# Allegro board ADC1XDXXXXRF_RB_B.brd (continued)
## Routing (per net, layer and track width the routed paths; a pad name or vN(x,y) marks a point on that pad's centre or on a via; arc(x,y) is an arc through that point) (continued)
FMC_DQ-5: length 142
  TOP w0.102: U5.C1 114.22,102.25 v1(113.71,102.76)
  SIG1 w0.102: v1(113.71,102.76) 114.1,103.15 114.1,103.4 102.59,114.91 66.5,114.91 66.28,115.13 66.28,115.42 66.18,115.52 65.98,115.52 65.87,115.42 65.87,115.13 65.65,114.91 65.28,114.91 65.06,115.13 65.06,115.42 64.96,115.52 64.76,115.52 64.65,115.42 64.65,115.13 64.43,114.91 64.06,114.91 63.84,115.13 63.84,115.42 63.74,115.52 63.54,115.52 63.44,115.42 63.44,115.13 63.21,114.91 62.84,114.91 62.62,115.13 62.62,115.42 62.52,115.52 62.32,115.52 62.22,115.42 62.22,115.13 62,114.91 61.62,114.91 61.4,115.13 61.4,115.42 61.3,115.52 61.1,115.52 61,115.42 61,115.13 60.78,114.91 60.4,114.91 60.18,115.13 60.18,115.42 60.08,115.52 59.88,115.52 59.78,115.42 59.78,115.13 59.56,114.91 59.19,114.91 58.96,115.13 58.96,115.42 58.86,115.52 58.66,115.52 58.56,115.42 58.56,115.13 58.34,114.91 57.97,114.91 57.75,115.13 57.75,115.42 57.64,115.52 57.44,115.52 57.34,115.42 57.34,115.13 57.12,114.91 56.75,114.91 56.53,115.13 56.53,115.42 56.42,115.52 56.22,115.52 56.12,115.42 56.12,115.13 55.9,114.91 55.53,114.91 55.31,115.13 55.31,115.42 55.21,115.52 55,115.52 54.9,115.42 54.9,115.13 54.68,114.91 54.31,114.91 54.09,115.13 54.09,115.42 53.99,115.52 53.78,115.52 53.68,115.42 53.68,115.13 53.46,114.91 53.09,114.91 52.87,115.13 52.87,115.42 52.77,115.52 52.56,115.52 52.46,115.42 52.46,115.13 52.24,114.91 51.87,114.91 51.65,115.13 51.65,115.42 51.55,115.52 51.34,115.52 51.24,115.42 51.24,115.13 51.02,114.91 50.65,114.91 50.43,115.13 50.43,115.42 50.33,115.52 50.13,115.52 50.02,115.42 50.02,115.13 49.8,114.91 49.43,114.91 49.21,115.13 49.21,115.42 49.11,115.52 48.91,115.52 48.8,115.42 48.8,115.13 48.58,114.91 48.21,114.91 47.99,115.13 47.99,115.42 47.89,115.52 47.69,115.52 47.59,115.42 47.59,115.13 47.37,114.91 46.99,114.91 46.77,115.13 46.77,115.42 46.67,115.52 46.47,115.52 46.37,115.42 46.37,115.13 46.15,114.91 11.65,114.91 11.53,114.79 11.53,106.35 11.66,106.22 19.35,106.22 19.46,106.32 19.46,106.65 19.35,106.76 v3(18.41,106.76)
  BOTTOM w0.102: FMC.K29 v3(18.41,106.76)
FMC_DQ-6: length 142
  TOP w0.102: v1(115.72,98.75) U5.F3
  SIG1 w0.102: v1(115.72,98.75) 115.86,98.75 116.12,98.49 116.12,94.56 115.9,94.35 109.45,94.35 98.84,104.95 62.94,104.95 62.83,105.05 62.83,106.15 62.61,106.38 62.24,106.38 62.02,106.15 62.02,105.05 61.92,104.95 61.72,104.95 61.61,105.05 61.61,106.15 61.39,106.38 61.02,106.38 60.8,106.15 60.8,105.05 60.7,104.95 60.5,104.95 60.4,105.05 60.4,106.1 60.17,106.32 59.8,106.32 59.58,106.1 59.58,105.05 59.48,104.95 59.28,104.95 59.18,105.05 59.18,106.1 58.96,106.32 58.58,106.32 58.36,106.1 58.36,105.05 58.26,104.95 58.06,104.95 57.96,105.05 57.96,106.1 57.74,106.32 57.36,106.32 57.14,106.1 57.14,105.05 57.04,104.95 56.84,104.95 56.74,105.05 56.74,106.1 56.52,106.32 56.15,106.32 55.92,106.1 55.92,105.05 55.82,104.95 55.62,104.95 55.52,105.05 55.52,106.1 55.3,106.32 54.93,106.32 54.71,106.1 54.71,105.05 54.6,104.95 54.4,104.95 54.3,105.05 54.3,106.1 54.08,106.32 53.71,106.32 53.49,106.1 53.49,105.05 53.38,104.95 53.18,104.95 53.08,105.05 53.08,106.1 52.86,106.32 52.49,106.32 52.27,106.1 52.27,105.05 52.17,104.95 51.96,104.95 51.86,105.05 51.86,106.1 51.64,106.32 51.27,106.32 51.05,106.1 51.05,105.05 50.95,104.95 50.74,104.95 50.64,105.05 50.64,106.1 50.42,106.32 50.05,106.32 49.83,106.1 49.83,105.05 49.73,104.95 49.52,104.95 49.42,105.05 49.42,106.1 49.2,106.32 48.83,106.32 48.61,106.1 48.61,105.05 48.51,104.95 48.3,104.95 48.2,105.05 48.2,106.1 47.98,106.32 47.61,106.32 47.39,106.1 47.39,105.05 47.29,104.95 47.09,104.95 46.98,105.05 46.98,106.1 46.76,106.32 46.39,106.32 46.17,106.1 46.17,105.05 46.07,104.95 18.52,104.95 18.41,105.05 v3(18.41,105.49)
  BOTTOM w0.102: FMC.J28 v3(18.41,105.49)
FMC_DQ-7: length 142.1
  TOP w0.102: v1(115.72,97.74) U5.G3
  SIG2 w0.102: v1(115.72,97.74) 115.72,97.48 115.59,97.35 104.59,97.35 96.99,104.95 90.98,104.95 90.88,105.05 90.88,105.37 90.66,105.59 90.29,105.59 90.07,105.37 90.07,105.05 89.97,104.95 89.76,104.95 89.66,105.05 89.66,105.37 89.44,105.59 89.07,105.59 88.85,105.37 88.85,105.05 88.75,104.95 88.54,104.95 88.44,105.05 88.44,105.37 88.22,105.59 87.85,105.59 87.63,105.37 87.63,105.05 87.53,104.95 87.33,104.95 87.22,105.05 87.22,105.39 87,105.61 86.63,105.61 86.41,105.39 86.41,105.05 86.31,104.95 86.11,104.95 86,105.05 86,105.39 85.78,105.61 85.41,105.61 85.19,105.39 85.19,105.05 85.09,104.95 84.89,104.95 84.79,105.05 84.79,105.39 84.56,105.61 84.19,105.61 83.97,105.39 83.97,105.05 83.87,104.95 83.67,104.95 83.57,105.05 83.57,105.39 83.35,105.61 82.97,105.61 82.75,105.39 82.75,105.05 82.65,104.95 82.45,104.95 82.35,105.05 82.35,105.39 82.13,105.61 81.75,105.61 81.53,105.39 81.53,105.05 81.43,104.95 81.23,104.95 81.13,105.05 81.13,105.39 80.91,105.61 80.54,105.61 80.31,105.39 80.31,105.05 80.21,104.95 80.01,104.95 79.91,105.05 79.91,105.39 79.69,105.61 79.32,105.61 79.1,105.39 79.1,105.05 78.99,104.95 78.79,104.95 78.69,105.05 78.69,105.39 78.47,105.61 78.1,105.61 77.88,105.39 77.88,105.05 77.77,104.95 77.57,104.95 77.47,105.05 77.47,105.39 77.25,105.61 76.88,105.61 76.66,105.39 76.66,105.05 76.56,104.95 76.35,104.95 76.25,105.05 76.25,105.39 76.03,105.61 75.66,105.61 75.44,105.39 75.44,105.05 75.34,104.95 75.13,104.95 75.03,105.05 75.03,105.39 74.81,105.61 74.44,105.61 74.22,105.39 74.22,105.05 74.12,104.95 73.91,104.95 73.81,105.05 73.81,105.39 73.59,105.61 73.22,105.61 73,105.39 73,105.05 72.9,104.95 72.69,104.95 72.59,105.05 72.59,105.39 72.37,105.61 72,105.61 71.78,105.39 71.78,105.05 71.68,104.95 71.48,104.95 71.37,105.05 71.37,105.39 71.15,105.61 70.78,105.61 70.56,105.39 70.56,105.05 70.46,104.95 70.26,104.95 70.15,105.05 70.15,105.39 69.93,105.61 69.56,105.61 69.34,105.39 69.34,105.05 69.24,104.95 69.04,104.95 68.94,105.05 68.94,105.39 68.72,105.61 68.34,105.61 68.12,105.39 68.12,105.05 68.02,104.95 67.82,104.95 67.72,105.05 67.72,105.39 67.5,105.61 67.12,105.61 66.9,105.39 66.9,105.05 66.8,104.95 66.6,104.95 66.5,105.05 66.5,105.39 66.28,105.61 65.9,105.61 65.68,105.39 65.68,105.05 65.58,104.95 65.38,104.95 65.28,105.05 65.28,105.39 65.06,105.61 64.69,105.61 64.47,105.39 64.47,105.05 64.36,104.95 64.16,104.95 64.06,105.05 64.06,105.39 63.84,105.61 63.47,105.61 63.25,105.39 63.25,105.05 63.14,104.95 62.94,104.95 62.84,105.05 62.84,105.39 62.62,105.61 62.25,105.61 62.03,105.39 62.03,105.05 61.93,104.95 61.72,104.95 61.62,105.05 61.62,105.39 61.4,105.61 61.03,105.61 60.81,105.39 60.81,105.05 60.71,104.95 60.5,104.95 60.4,105.05 60.4,105.39 60.18,105.61 59.81,105.61 59.59,105.39 59.59,105.05 59.49,104.95 59.28,104.95 59.18,105.05 59.18,105.39 58.96,105.61 58.59,105.61 58.37,105.39 58.37,105.05 58.27,104.95 58.06,104.95 57.96,105.05 57.96,105.39 57.74,105.61 57.37,105.61 57.15,105.39 57.15,105.05 57.05,104.95 56.85,104.95 56.74,105.05 56.74,105.39 56.52,105.61 56.15,105.61 55.93,105.39 55.93,105.05 55.83,104.95 55.63,104.95 55.52,105.05 55.52,105.39 55.3,105.61 54.93,105.61 54.71,105.39 54.71,105.05 54.61,104.95 54.41,104.95 54.31,105.05 54.31,105.39 54.08,105.61 53.71,105.61 53.49,105.39 53.49,105.05 53.39,104.95 53.19,104.95 53.09,105.05 53.09,105.39 52.87,105.61 52.49,105.61 52.27,105.39 52.27,105.05 52.17,104.95 51.97,104.95 51.87,105.05 51.87,105.39 51.65,105.61 51.27,105.61 51.05,105.39 51.05,105.05 50.95,104.95 50.75,104.95 50.65,105.05 50.65,105.39 50.43,105.61 50.06,105.61 49.83,105.39 49.83,105.05 49.73,104.95 49.53,104.95 49.43,105.05 49.43,105.39 49.21,105.61 48.84,105.61 48.62,105.39 48.62,105.05 48.51,104.95 48.31,104.95 48.21,105.05 48.21,105.39 47.99,105.61 47.62,105.61 47.4,105.39 47.4,105.05 47.29,104.95 47.09,104.95 46.99,105.05 46.99,105.39 46.77,105.61 46.4,105.61 46.18,105.39 46.18,105.05 46.08,104.95 14.35,104.95 14.2,105.11 14.2,105.31 14.38,105.49 v3(14.61,105.49)
  BOTTOM w0.102: FMC.F29 v3(14.61,105.49)
FMC_DQ-8: length 142.1
  TOP w0.102: v1(113.72,99.75) U5.F1
  SIG2 w0.102: v3(12.06,105.49) 12.19,105.49 12.29,105.38 12.29,105.05 12.19,104.95 10.41,104.95 10.26,105.11 10.26,109.69 10.4,109.83 14.05,109.83 15.32,108.56 46.16,108.56 46.38,108.78 46.38,109.02 46.48,109.12 46.69,109.12 46.79,109.02 46.79,108.78 47.01,108.56 47.38,108.56 47.6,108.78 47.6,109.02 47.7,109.12 47.9,109.12 48.01,109.02 48.01,108.78 48.23,108.56 48.6,108.56 48.82,108.78 48.82,109.02 48.92,109.12 49.12,109.12 49.23,109.02 49.23,108.78 49.45,108.56 49.82,108.56 50.04,108.78 50.04,109.02 50.14,109.12 50.34,109.12 50.44,109.02 50.44,108.78 50.66,108.56 51.04,108.56 51.26,108.78 51.26,109.02 51.36,109.12 51.56,109.12 51.66,109.02 51.66,108.78 51.88,108.56 52.26,108.56 52.48,108.78 52.48,109.02 52.58,109.12 52.78,109.12 52.88,109.02 52.88,108.78 53.1,108.56 53.48,108.56 53.7,108.78 53.7,109.02 53.8,109.12 54,109.12 54.1,109.02 54.1,108.78 54.32,108.56 54.69,108.56 54.91,108.78 54.91,109.02 55.02,109.12 55.22,109.12 55.32,109.02 55.32,108.78 55.54,108.56 55.91,108.56 56.13,108.78 56.13,109.02 56.24,109.12 56.44,109.12 56.54,109.02 56.54,108.78 56.76,108.56 57.13,108.56 57.35,108.78 57.35,109.02 57.45,109.12 57.66,109.12 57.76,109.02 57.76,108.78 57.98,108.56 58.35,108.56 58.57,108.78 58.57,109.02 58.67,109.12 58.88,109.12 58.98,109.02 58.98,108.78 59.2,108.56 59.57,108.56 59.79,108.78 59.79,109.02 59.89,109.12 60.1,109.12 60.2,109.02 60.2,108.78 60.42,108.56 60.79,108.56 61.01,108.78 61.01,109.02 61.11,109.12 61.32,109.12 61.42,109.02 61.42,108.78 61.64,108.56 62.01,108.56 62.23,108.78 62.23,109.02 62.33,109.12 62.53,109.12 62.64,109.02 62.64,108.78 62.86,108.56 63.23,108.56 63.45,108.78 63.45,109.02 63.55,109.12 63.75,109.12 63.86,109.02 63.86,108.78 64.08,108.56 64.45,108.56 64.67,108.78 64.67,109.02 64.77,109.12 64.97,109.12 65.07,109.02 65.07,108.78 65.3,108.56 65.67,108.56 65.89,108.78 65.89,109.02 65.99,109.12 66.19,109.12 66.29,109.02 66.29,108.78 66.51,108.56 66.89,108.56 67.11,108.78 67.11,109.02 67.21,109.12 67.41,109.12 67.51,109.02 67.51,108.78 67.73,108.56 68.11,108.56 68.33,108.78 68.33,109.02 68.43,109.12 68.63,109.12 68.73,109.02 68.73,108.78 68.95,108.56 69.32,108.56 69.55,108.78 69.55,109.02 69.65,109.12 69.85,109.12 69.95,109.02 69.95,108.78 70.17,108.56 70.54,108.56 70.76,108.78 70.76,109.02 70.87,109.12 71.07,109.12 71.17,109.02 71.17,108.78 71.39,108.56 71.76,108.56 71.98,108.78 71.98,109.02 72.09,109.12 72.29,109.12 72.39,109.02 72.39,108.78 72.61,108.56 72.98,108.56 73.2,108.78 73.2,109.02 73.3,109.12 73.51,109.12 73.61,109.02 73.61,108.78 73.83,108.56 74.2,108.56 74.42,108.78 74.42,109.02 74.52,109.12 74.73,109.12 74.83,109.02 74.83,108.78 75.05,108.56 75.42,108.56 75.64,108.78 75.64,109.02 75.74,109.12 75.95,109.12 76.05,109.02 76.05,108.78 76.27,108.56 76.64,108.56 76.86,108.78 76.86,109.02 76.96,109.12 77.17,109.12 77.27,109.02 77.27,108.78 77.49,108.56 77.86,108.56 78.08,108.78 78.08,109.02 78.18,109.12 78.38,109.12 78.49,109.02 78.49,108.78 78.71,108.56 79.08,108.56 79.3,108.78 79.3,108.99 79.4,109.09 79.6,109.09 79.71,108.99 79.71,108.78 79.93,108.56 80.3,108.56 80.52,108.78 80.52,108.99 80.62,109.09 80.82,109.09 80.92,108.99 80.92,108.78 81.14,108.56 81.52,108.56 81.74,108.78 81.74,108.99 81.84,109.09 82.04,109.09 82.14,108.99 82.14,108.78 82.36,108.56 82.74,108.56 82.96,108.78 82.96,108.99 83.06,109.09 83.26,109.09 83.36,108.99 83.36,108.78 83.58,108.56 83.96,108.56 84.18,108.78 84.18,108.99 84.28,109.09 84.48,109.09 84.58,108.99 84.58,108.78 84.8,108.56 85.17,108.56 85.39,108.78 85.39,108.99 85.5,109.09 85.7,109.09 85.8,108.99 85.8,108.78 86.02,108.56 86.39,108.56 86.61,108.78 86.61,108.99 86.72,109.09 86.92,109.09 87.02,108.99 87.02,108.78 87.24,108.56 87.61,108.56 87.83,108.78 87.83,108.99 87.93,109.09 88.14,109.09 88.24,108.99 88.24,108.78 88.46,108.56 95.22,108.56 103.62,100.15 113.31,100.15 113.71,99.75 v1(113.72,99.75)
  BOTTOM w0.102: FMC.E28 v3(12.06,105.49)
FMC_DQ-9: length 142.1
  TOP w0.102: U5.C10 v1(122.71,102.76)
  SIG2 w0.102: v1(122.71,102.76) 122.31,102.36 121.46,102.36 121.1,102 121.1,100.47 120.99,100.35 116.54,100.35 115.54,101.35 103.71,101.35 95.03,110.03 89.76,110.03 89.66,110.13 89.66,110.4 89.44,110.62 89.07,110.62 88.85,110.4 88.85,110.13 88.75,110.03 88.54,110.03 88.44,110.13 88.44,110.4 88.22,110.62 87.85,110.62 87.63,110.4 87.63,110.13 87.53,110.03 87.33,110.03 87.22,110.13 87.22,110.4 87,110.62 86.63,110.62 86.41,110.4 86.41,110.13 86.31,110.03 86.11,110.03 86,110.13 86,110.4 85.78,110.62 85.41,110.62 85.19,110.4 85.19,110.13 85.09,110.03 84.89,110.03 84.79,110.13 84.79,110.4 84.56,110.62 84.19,110.62 83.97,110.4 83.97,110.13 83.87,110.03 83.67,110.03 83.57,110.13 83.57,110.42 83.35,110.64 82.97,110.64 82.75,110.42 82.75,110.13 82.65,110.03 82.45,110.03 82.35,110.13 82.35,110.42 82.13,110.64 81.75,110.64 81.53,110.42 81.53,110.13 81.43,110.03 81.23,110.03 81.13,110.13 81.13,110.42 80.91,110.64 80.54,110.64 80.31,110.42 80.31,110.13 80.21,110.03 80.01,110.03 79.91,110.13 79.91,110.42 79.69,110.64 79.32,110.64 79.1,110.42 79.1,110.13 78.99,110.03 78.79,110.03 78.69,110.13 78.69,110.42 78.47,110.64 78.1,110.64 77.88,110.42 77.88,110.13 77.77,110.03 77.57,110.03 77.47,110.13 77.47,110.42 77.25,110.64 76.88,110.64 76.66,110.42 76.66,110.13 76.56,110.03 76.35,110.03 76.25,110.13 76.25,110.42 76.03,110.64 75.66,110.64 75.44,110.42 75.44,110.13 75.34,110.03 75.13,110.03 75.03,110.13 75.03,110.42 74.81,110.64 74.44,110.64 74.22,110.42 74.22,110.13 74.12,110.03 73.91,110.03 73.81,110.13 73.81,110.42 73.59,110.64 73.22,110.64 73,110.42 73,110.13 72.9,110.03 72.69,110.03 72.59,110.13 72.59,110.42 72.37,110.64 72,110.64 71.78,110.42 71.78,110.13 71.68,110.03 71.48,110.03 71.37,110.13 71.37,110.42 71.15,110.64 70.78,110.64 70.56,110.42 70.56,110.13 70.46,110.03 70.26,110.03 70.15,110.13 70.15,110.42 69.93,110.64 69.56,110.64 69.34,110.42 69.34,110.13 69.24,110.03 69.04,110.03 68.94,110.13 68.94,110.42 68.72,110.64 68.34,110.64 68.12,110.42 68.12,110.13 68.02,110.03 67.82,110.03 67.72,110.13 67.72,110.42 67.5,110.64 67.12,110.64 66.9,110.42 66.9,110.13 66.8,110.03 66.6,110.03 66.5,110.13 66.5,110.42 66.28,110.64 65.9,110.64 65.68,110.42 65.68,110.13 65.58,110.03 65.38,110.03 65.28,110.13 65.28,110.42 65.06,110.64 64.69,110.64 64.47,110.42 64.47,110.13 64.36,110.03 64.16,110.03 64.06,110.13 64.06,110.42 63.84,110.64 63.47,110.64 63.25,110.42 63.25,110.13 63.14,110.03 62.94,110.03 62.84,110.13 62.84,110.42 62.62,110.64 62.25,110.64 62.03,110.42 62.03,110.13 61.93,110.03 61.72,110.03 61.62,110.13 61.62,110.42 61.4,110.64 61.03,110.64 60.81,110.42 60.81,110.13 60.71,110.03 60.5,110.03 60.4,110.13 60.4,110.42 60.18,110.64 59.81,110.64 59.59,110.42 59.59,110.13 59.49,110.03 59.28,110.03 59.18,110.13 59.18,110.42 58.96,110.64 58.59,110.64 58.37,110.42 58.37,110.13 58.27,110.03 58.06,110.03 57.96,110.13 57.96,110.42 57.74,110.64 57.37,110.64 57.15,110.42 57.15,110.13 57.05,110.03 56.85,110.03 56.74,110.13 56.74,110.42 56.52,110.64 56.15,110.64 55.93,110.42 55.93,110.13 55.83,110.03 55.63,110.03 55.52,110.13 55.52,110.42 55.3,110.64 54.93,110.64 54.71,110.42 54.71,110.13 54.61,110.03 54.41,110.03 54.31,110.13 54.31,110.42 54.08,110.64 53.71,110.64 53.49,110.42 53.49,110.13 53.39,110.03 53.19,110.03 53.09,110.13 53.09,110.42 52.87,110.64 52.49,110.64 52.27,110.42 52.27,110.13 52.17,110.03 51.97,110.03 51.87,110.13 51.87,110.42 51.65,110.64 51.27,110.64 51.05,110.42 51.05,110.13 50.95,110.03 50.75,110.03 50.65,110.13 50.65,110.42 50.43,110.64 50.06,110.64 49.83,110.42 49.83,110.13 49.73,110.03 49.53,110.03 49.43,110.13 49.43,110.42 49.21,110.64 48.84,110.64 48.62,110.42 48.62,110.13 48.51,110.03 48.31,110.03 48.21,110.13 48.21,110.42 47.99,110.64 47.62,110.64 47.4,110.42 47.4,110.13 47.29,110.03 47.09,110.03 46.99,110.13 46.99,110.42 46.77,110.64 46.4,110.64 46.18,110.42 46.18,110.13 46.08,110.03 18.95,110.03 v3(18.41,110.57)
  BOTTOM w0.102: FMC.K32 v3(18.41,110.57)
FMC_DQ-10: length 142
  TOP w0.102: v1(113.72,97.74) U5.G1
  SIG1 w0.102: v3(17.14,109.3) 17.68,108.76 19.19,108.76 20.46,110.03 47.26,110.03 47.37,110.13 47.37,110.47 47.59,110.69 47.96,110.69 48.18,110.47 48.18,110.13 48.28,110.03 48.48,110.03 48.58,110.13 48.58,110.47 48.8,110.69 49.18,110.69 49.4,110.47 49.4,110.13 49.5,110.03 49.7,110.03 49.8,110.13 49.8,110.47 50.02,110.69 50.4,110.69 50.62,110.47 50.62,110.13 50.72,110.03 50.92,110.03 51.02,110.13 51.02,110.47 51.24,110.69 51.62,110.69 51.84,110.47 51.84,110.13 51.94,110.03 52.14,110.03 52.24,110.13 52.24,110.47 52.46,110.69 52.83,110.69 53.05,110.47 53.05,110.13 53.16,110.03 53.36,110.03 53.46,110.13 53.46,110.47 53.68,110.69 54.05,110.69 54.27,110.47 54.27,110.13 54.38,110.03 54.58,110.03 54.68,110.13 54.68,110.47 54.9,110.69 55.27,110.69 55.49,110.47 55.49,110.13 55.59,110.03 55.8,110.03 55.9,110.13 55.9,110.47 56.12,110.69 56.49,110.69 56.71,110.47 56.71,110.13 56.81,110.03 57.02,110.03 57.12,110.13 57.12,110.47 57.34,110.69 57.71,110.69 57.93,110.47 57.93,110.13 58.03,110.03 58.24,110.03 58.34,110.13 58.34,110.47 58.56,110.69 58.93,110.69 59.15,110.47 59.15,110.13 59.25,110.03 59.46,110.03 59.56,110.13 59.56,110.45 59.78,110.67 60.15,110.67 60.37,110.45 60.37,110.13 60.47,110.03 60.67,110.03 60.78,110.13 60.78,110.45 61,110.67 61.37,110.67 61.59,110.45 61.59,110.13 61.69,110.03 61.89,110.03 62,110.13 62,110.45 62.22,110.67 62.59,110.67 62.81,110.45 62.81,110.13 62.91,110.03 63.11,110.03 63.21,110.13 63.21,110.45 63.44,110.67 63.81,110.67 64.03,110.45 64.03,110.13 64.13,110.03 64.33,110.03 64.43,110.13 64.43,110.45 64.65,110.67 65.03,110.67 65.25,110.45 65.25,110.13 65.35,110.03 65.55,110.03 65.65,110.13 65.65,110.45 65.87,110.67 66.25,110.67 66.47,110.45 66.47,110.13 66.57,110.03 66.77,110.03 66.87,110.13 66.87,110.45 67.09,110.67 67.46,110.67 67.69,110.45 67.69,110.13 67.79,110.03 67.99,110.03 68.09,110.13 68.09,110.45 68.31,110.67 68.68,110.67 68.9,110.45 68.9,110.13 69.01,110.03 69.21,110.03 69.31,110.13 69.31,110.45 69.53,110.67 69.9,110.67 70.12,110.45 70.12,110.13 70.23,110.03 70.43,110.03 70.53,110.13 70.53,110.45 70.75,110.67 71.12,110.67 71.34,110.45 71.34,110.13 71.44,110.03 71.65,110.03 71.75,110.13 71.75,110.45 71.97,110.67 72.34,110.67 72.56,110.45 72.56,110.13 72.66,110.03 72.87,110.03 72.97,110.13 72.97,110.45 73.19,110.67 73.56,110.67 73.78,110.45 73.78,110.13 73.88,110.03 74.09,110.03 74.19,110.13 74.19,110.45 74.41,110.67 74.78,110.67 75,110.45 75,110.13 75.1,110.03 75.31,110.03 75.41,110.13 75.41,110.45 75.63,110.67 76,110.67 76.22,110.45 76.22,110.13 76.32,110.03 76.52,110.03 76.63,110.13 76.63,110.45 76.85,110.67 77.22,110.67 77.44,110.45 77.44,110.13 77.54,110.03 77.74,110.03 77.85,110.13 77.85,110.45 78.07,110.67 78.44,110.67 78.66,110.45 78.66,110.13 78.76,110.03 78.96,110.03 79.06,110.13 79.06,110.45 79.28,110.67 79.66,110.67 79.88,110.45 79.88,110.13 79.98,110.03 80.18,110.03 80.28,110.13 80.28,110.45 80.5,110.67 80.88,110.67 81.1,110.45 81.1,110.13 81.2,110.03 81.4,110.03 81.5,110.13 81.5,110.45 81.72,110.67 82.1,110.67 82.32,110.45 82.32,110.13 82.42,110.03 82.62,110.03 82.72,110.13 82.72,110.45 82.94,110.67 83.31,110.67 83.53,110.45 83.53,110.13 83.64,110.03 83.84,110.03 83.94,110.13 83.94,110.45 84.16,110.67 84.53,110.67 84.75,110.45 84.75,110.13 84.86,110.03 85.06,110.03 85.16,110.13 85.16,110.45 85.38,110.67 85.75,110.67 85.97,110.45 85.97,110.13 86.07,110.03 86.28,110.03 86.38,110.13 86.38,110.45 86.6,110.67 86.97,110.67 87.19,110.45 87.19,110.13 87.29,110.03 87.5,110.03 87.6,110.13 87.6,110.45 87.82,110.67 88.19,110.67 88.41,110.45 88.41,110.13 88.51,110.03 88.72,110.03 88.82,110.13 88.82,110.45 89.04,110.67 89.41,110.67 89.63,110.45 89.63,110.13 89.73,110.03 89.94,110.03 90.04,110.13 90.04,110.45 90.26,110.67 90.63,110.67 90.85,110.45 90.85,110.13 90.95,110.03 91.15,110.03 91.26,110.13 91.26,110.45 91.48,110.67 91.85,110.67 92.07,110.45 92.07,110.13 92.17,110.03 92.37,110.03 92.48,110.13 92.48,110.45 92.7,110.67 93.07,110.67 93.29,110.45 93.29,110.13 93.39,110.03 93.59,110.03 93.69,110.13 93.69,110.45 93.92,110.67 94.29,110.67 94.51,110.45 94.51,110.13 94.61,110.03 94.81,110.03 94.91,110.13 94.91,110.45 95.13,110.67 95.51,110.67 95.73,110.45 95.73,110.13 95.83,110.03 96.03,110.03 96.13,110.13 96.13,110.45 96.35,110.67 96.73,110.67 96.95,110.45 96.95,110.13 97.05,110.03 97.25,110.03 97.35,110.13 97.35,110.45 97.57,110.67 97.94,110.67 98.17,110.45 98.17,110.13 98.27,110.03 99.86,110.03 111.83,98.06 113.4,98.06 v1(113.72,97.74)
  BOTTOM w0.102: FMC.J31 v3(17.14,109.3)
FMC_DQ-11: length 142.1
  TOP w0.102: v1(115.72,96.74) U5.H3
  SIG2 w0.102: v1(115.72,96.74) 116.15,96.74 116.56,97.16 116.81,97.16 117.12,97.46 117.12,98.02 116.99,98.15 104.55,98.15 96.67,106.02 56.76,106.02 56.54,106.24 56.54,107.62 56.44,107.72 56.24,107.72 56.13,107.62 56.13,106.24 55.91,106.02 55.54,106.02 55.32,106.24 55.32,107.62 55.22,107.72 55.02,107.72 54.91,107.62 54.91,106.24 54.69,106.02 54.32,106.02 54.1,106.24 54.1,107.62 54,107.72 53.8,107.72 53.7,107.62 53.7,106.24 53.48,106.02 53.1,106.02 52.88,106.24 52.88,107.59 52.78,107.7 52.58,107.7 52.48,107.59 52.48,106.24 52.26,106.02 51.88,106.02 51.66,106.24 51.66,107.59 51.56,107.7 51.36,107.7 51.26,107.59 51.26,106.24 51.04,106.02 50.66,106.02 50.44,106.24 50.44,107.59 50.34,107.7 50.14,107.7 50.04,107.59 50.04,106.24 49.82,106.02 49.45,106.02 49.23,106.24 49.23,107.59 49.12,107.7 48.92,107.7 48.82,107.59 48.82,106.24 48.6,106.02 48.23,106.02 48.01,106.24 48.01,107.59 47.9,107.7 47.7,107.7 47.6,107.59 47.6,106.24 47.38,106.02 47.01,106.02 46.79,106.24 46.79,107.59 46.69,107.7 46.48,107.7 46.38,107.59 46.38,106.24 46.16,106.02 12.83,106.02 12.57,106.27 12.57,108.53 v3(13.34,109.3)
  BOTTOM w0.102: FMC.F32 v3(13.34,109.3)
FMC_DQD+0: length 142
  TOP w0.102: v1(122.72,99.75) U5.F10
  SIG3 w0.102: v1(122.72,99.75) 122.73,99.77 122.73,100.05 122.66,100.13 122.52,100.13 122.31,99.92 122.31,92.48 121.98,92.15 119.54,92.15 119.31,91.91 119.31,91.48 118.97,91.14 76.18,91.14 61.21,76.17 55.82,76.17 55.72,76.07 55.72,75.25 55.5,75.03 55.13,75.03 54.91,75.25 54.91,76.07 54.81,76.17 54.6,76.17 54.5,76.07 54.5,75.25 54.28,75.03 53.91,75.03 53.69,75.25 53.69,76.07 53.59,76.17 53.39,76.17 53.28,76.07 53.28,75.25 53.06,75.03 52.69,75.03 52.47,75.25 52.47,76.07 52.37,76.17 52.17,76.17 52.06,76.07 52.06,75.25 51.84,75.03 51.47,75.03 51.25,75.25 51.25,76.07 51.15,76.17 50.95,76.17 50.85,76.07 50.85,75.25 50.62,75.03 50.25,75.03 50.03,75.25 50.03,76.07 49.93,76.17 49.73,76.17 49.63,76.07 49.63,75.25 49.41,75.03 49.03,75.03 48.81,75.25 48.81,76.07 48.71,76.17 48.51,76.17 48.41,76.07 48.41,75.25 48.19,75.03 47.81,75.03 47.59,75.25 47.59,76.07 47.49,76.17 46.44,76.17 43.26,73 12.6,73 v3(12.06,72.47)
  BOTTOM w0.102: FMC.E2 v3(12.06,72.47)
FMC_DQD+1: length 142.1
  TOP w0.102: U5.E9 122.18,100.24 v1(121.7,99.76)
  SIG3 w0.102: v1(121.7,99.76) 121.28,99.34 72.56,99.34 72.14,98.92 72.14,97.63 72.03,97.53 71.7,97.53 71.48,97.31 71.48,96.94 71.7,96.71 72.03,96.71 72.14,96.61 72.14,96.41 72.03,96.31 71.7,96.31 71.48,96.09 71.48,95.72 71.7,95.5 72.03,95.5 72.14,95.39 72.14,95.19 72.03,95.09 71.7,95.09 71.48,94.87 71.48,94.5 71.7,94.28 72.03,94.28 72.14,94.17 72.14,93.97 72.03,93.87 71.7,93.87 71.48,93.65 71.48,93.28 71.7,93.06 72.03,93.06 72.14,92.96 72.14,92.75 72.03,92.65 71.7,92.65 71.48,92.43 71.48,92.06 71.7,91.84 72.03,91.84 72.14,91.74 72.14,91.53 72.03,91.43 71.7,91.43 71.48,91.21 71.48,90.84 71.7,90.62 72.03,90.62 72.14,90.52 72.14,90.23 61.46,79.55 60.7,79.55 60.6,79.65 60.6,79.99 60.38,80.21 60.01,80.21 59.79,79.99 59.79,79.35 59.68,79.25 59.48,79.25 59.38,79.35 59.38,79.99 59.16,80.21 58.79,80.21 58.57,79.99 58.57,79.35 58.47,79.25 58.26,79.25 58.16,79.35 58.16,79.99 57.94,80.21 57.57,80.21 57.35,79.99 57.35,79.35 57.25,79.25 57.04,79.25 56.94,79.35 56.94,79.99 56.72,80.21 56.35,80.21 56.13,79.99 56.13,79.35 56.03,79.25 55.82,79.25 55.72,79.35 55.72,79.99 55.5,80.21 55.13,80.21 54.91,79.99 54.91,79.35 54.81,79.25 54.6,79.25 54.5,79.35 54.5,79.99 54.28,80.21 53.91,80.21 53.69,79.99 53.69,79.38 53.59,79.27 53.39,79.27 53.28,79.38 53.28,79.99 53.06,80.21 52.69,80.21 52.47,79.99 52.47,79.38 52.37,79.27 52.17,79.27 52.06,79.38 52.06,79.99 51.84,80.21 51.47,80.21 51.25,79.99 51.25,79.38 51.15,79.27 50.95,79.27 50.85,79.38 50.85,79.99 50.62,80.21 50.25,80.21 50.03,79.99 50.03,79.38 49.93,79.27 49.73,79.27 49.63,79.38 49.63,79.99 49.41,80.21 49.03,80.21 48.81,79.99 48.81,79.38 48.71,79.27 48.51,79.27 48.41,79.38 48.41,79.99 48.19,80.21 47.81,80.21 47.59,79.99 47.59,79.65 47.49,79.55 46.54,79.55 45.37,80.72 19.34,80.72 19.02,80.4 19.02,79.47 19.68,78.82 v3(19.68,78.82)
  BOTTOM w0.102: FMC.K7 v3(19.68,78.82)
FMC_DQD+2: length 142.1
  TOP w0.102: v1(120.72,98.75) U5.F8
  SIG3 w0.102: v1(120.72,98.75) 121.31,98.15 121.31,94.3 120.15,93.14 118.5,93.14 118.31,92.95 118.31,92.39 118.06,92.14 75.76,92.14 62.08,78.46 60.09,78.46 59.99,78.36 59.99,77.33 59.77,77.11 59.4,77.11 59.18,77.33 59.18,78.36 59.08,78.46 58.87,78.46 58.77,78.36 58.77,77.33 58.55,77.11 58.18,77.11 57.96,77.33 57.96,78.36 57.86,78.46 57.65,78.46 57.55,78.36 57.55,77.33 57.33,77.11 56.96,77.11 56.74,77.33 56.74,78.36 56.64,78.46 56.43,78.46 56.33,78.36 56.33,77.33 56.11,77.11 55.74,77.11 55.52,77.33 55.52,78.36 55.42,78.46 55.21,78.46 55.11,78.36 55.11,77.33 54.89,77.11 54.52,77.11 54.3,77.33 54.3,78.36 54.2,78.46 54,78.46 53.89,78.36 53.89,77.33 53.67,77.11 53.3,77.11 53.08,77.33 53.08,78.36 52.98,78.46 52.78,78.46 52.67,78.36 52.67,77.33 52.45,77.11 52.08,77.11 51.86,77.33 51.86,78.36 51.76,78.46 51.56,78.46 51.46,78.36 51.46,77.31 51.23,77.09 50.86,77.09 50.64,77.31 50.64,78.36 50.54,78.46 50.34,78.46 50.24,78.36 50.24,77.31 50.02,77.09 49.64,77.09 49.42,77.31 49.42,78.36 49.32,78.46 49.12,78.46 49.02,78.36 49.02,77.31 48.8,77.09 48.42,77.09 48.2,77.31 48.2,78.36 48.1,78.46 47.9,78.46 47.8,78.36 47.8,77.31 47.58,77.09 47.21,77.09 46.98,77.31 46.98,78.36 46.88,78.46 45.91,78.46 45.52,78.08 18.95,78.08 v3(18.41,77.55)
  BOTTOM w0.102: FMC.J6 v3(18.41,77.55)
FMC_DQD+3: length 142.1
  TOP w0.102: U5.D9 v1(121.71,101.75)
  SIG3 w0.102: v3(14.61,77.55) 15.14,78.08 16.31,78.08 16.61,78.38 16.61,79.2 16.76,79.35 17.58,79.35 17.88,79.65 17.88,80.26 18.82,81.2 46.13,81.2 46.71,80.62 47.58,80.62 47.8,80.84 47.8,81.18 47.9,81.28 48.1,81.28 48.2,81.18 48.2,80.84 48.42,80.62 48.8,80.62 49.02,80.84 49.02,81.18 49.12,81.28 49.32,81.28 49.42,81.18 49.42,80.84 49.64,80.62 50.02,80.62 50.24,80.84 50.24,81.18 50.34,81.28 50.54,81.28 50.64,81.18 50.64,80.84 50.86,80.62 51.23,80.62 51.46,80.84 51.46,81.18 51.56,81.28 51.76,81.28 51.86,81.18 51.86,80.84 52.08,80.62 52.45,80.62 52.67,80.84 52.67,81.18 52.78,81.28 52.98,81.28 53.08,81.18 53.08,80.84 53.3,80.62 53.67,80.62 53.89,80.84 53.89,81.18 54,81.28 54.2,81.28 54.3,81.18 54.3,80.84 54.52,80.62 54.89,80.62 55.11,80.84 55.11,81.18 55.21,81.28 55.42,81.28 55.52,81.18 55.52,80.84 55.74,80.62 56.11,80.62 56.33,80.84 56.33,81.18 56.43,81.28 56.64,81.28 56.74,81.18 56.74,80.84 56.96,80.62 57.33,80.62 57.55,80.84 57.55,81.15 57.65,81.25 57.86,81.25 57.96,81.15 57.96,80.84 58.18,80.62 58.55,80.62 58.77,80.84 58.77,81.15 58.87,81.25 59.08,81.25 59.18,81.15 59.18,80.84 59.4,80.62 59.77,80.62 59.99,80.84 59.99,81.15 60.09,81.25 60.29,81.25 60.4,81.15 60.4,80.84 60.62,80.62 61.39,80.62 71.07,90.3 71.07,91.82 70.85,92.04 70.54,92.04 70.43,92.14 70.43,92.35 70.54,92.45 70.85,92.45 71.07,92.67 71.07,93.04 70.85,93.26 70.54,93.26 70.43,93.36 70.43,93.56 70.54,93.67 70.85,93.67 71.07,93.89 71.07,94.26 70.85,94.48 70.54,94.48 70.43,94.58 70.43,94.78 70.54,94.89 70.85,94.89 71.07,95.11 71.07,95.48 70.85,95.7 70.54,95.7 70.43,95.8 70.43,96 70.54,96.1 70.85,96.1 71.07,96.33 71.07,96.7 70.85,96.92 70.54,96.92 70.43,97.02 70.43,97.22 70.54,97.32 70.85,97.32 71.07,97.54 71.07,97.92 70.85,98.14 70.54,98.14 70.43,98.24 70.43,98.44 70.54,98.54 70.85,98.54 71.07,98.76 71.07,99.85 71.37,100.15 119.97,100.15 120.3,100.48 120.3,100.91 120.54,101.15 120.97,101.15 121.31,101.49 121.31,101.93 121.41,102.03 121.62,102.03 121.71,101.94 v1(121.71,101.75)
  BOTTOM w0.102: FMC.F7 v3(14.61,77.55)
FMC_DQD+4: length 142.1
  TOP w0.102: U5.D8 121.22,101.24 v1(120.71,101.75)
  SIG3 w0.102: v1(120.71,101.75) 120.27,101.75 119.67,102.36 107.77,102.36 107.31,102.82 68.8,102.82 68.33,102.34 68.33,101.29 68.22,101.18 67.89,101.18 67.67,100.96 67.67,100.59 67.89,100.37 68.22,100.37 68.33,100.27 68.33,100.07 68.22,99.97 67.89,99.97 67.67,99.75 67.67,99.37 67.89,99.15 68.22,99.15 68.33,99.05 68.33,98.85 68.22,98.75 67.91,98.75 67.69,98.53 67.69,98.15 67.91,97.93 68.22,97.93 68.33,97.83 68.33,97.63 68.22,97.53 67.91,97.53 67.69,97.31 67.69,96.94 67.91,96.71 68.22,96.71 68.33,96.61 68.33,96.41 68.22,96.31 67.91,96.31 67.69,96.09 67.69,95.72 67.91,95.5 68.22,95.5 68.33,95.39 68.33,95.19 68.22,95.09 67.91,95.09 67.69,94.87 67.69,94.5 67.91,94.28 68.22,94.28 68.33,94.17 68.33,93.97 68.22,93.87 67.91,93.87 67.69,93.65 67.69,93.28 67.91,93.06 68.22,93.06 68.33,92.96 68.33,92.75 68.22,92.65 67.91,92.65 67.69,92.43 67.69,92.06 67.91,91.84 68.22,91.84 68.33,91.74 68.33,90.69 61.54,83.9 v3(61.49,83.9)
  BOTTOM w0.102: FMC.E6 12.19,77.42 11.2,77.42 10.92,77.14 10.92,75.34 11.13,75.13 13.13,75.13 13.46,74.8 13.46,74.19 13.77,73.89 51.92,73.89 61.49,83.46 v3(61.49,83.9)
FMC_DQD+5: length 142.1
  TOP w0.102: v1(119.71,103.76) 120.22,103.25 U5.B7
  SIG3 w0.102: v1(119.71,103.76) 119.31,103.36 114.52,103.36 113.79,104.09 74.55,104.09 74.44,104.19 74.44,104.48 74.22,104.7 73.85,104.7 73.63,104.48 73.63,104.19 73.53,104.09 73.33,104.09 73.22,104.19 73.22,104.48 73,104.7 72.63,104.7 72.41,104.48 72.41,104.19 72.31,104.09 72.11,104.09 72.01,104.19 72.01,104.5 71.79,104.72 71.41,104.72 71.19,104.5 71.19,104.19 71.09,104.09 70.89,104.09 70.79,104.19 70.79,104.5 70.57,104.72 70.19,104.72 69.97,104.5 69.97,104.19 69.87,104.09 69.67,104.09 69.57,104.19 69.57,104.5 69.35,104.72 68.97,104.72 68.75,104.5 68.75,104.19 68.65,104.09 67.51,104.09 67.06,103.64 67.06,102.51 66.95,102.4 66.62,102.4 66.4,102.18 66.4,101.81 66.62,101.59 66.95,101.59 67.06,101.49 67.06,101.29 66.95,101.18 66.62,101.18 66.4,100.96 66.4,100.59 66.62,100.37 66.95,100.37 67.06,100.27 67.06,100.07 66.95,99.97 66.62,99.97 66.4,99.75 66.4,99.37 66.62,99.15 66.95,99.15 67.06,99.05 67.06,98.85 66.95,98.75 66.62,98.75 66.4,98.53 66.4,98.15 66.62,97.93 66.95,97.93 67.06,97.83 67.06,97.63 66.95,97.53 66.62,97.53 66.4,97.31 66.4,96.94 66.62,96.71 66.95,96.71 67.06,96.61 67.06,96.41 66.95,96.31 66.62,96.31 66.4,96.09 66.4,95.72 66.62,95.5 66.95,95.5 67.06,95.39 67.06,95.19 66.95,95.09 66.62,95.09 66.4,94.87 66.4,94.5 66.62,94.28 66.95,94.28 67.06,94.17 67.06,93.97 66.95,93.87 66.62,93.87 66.4,93.65 66.4,93.28 66.62,93.06 66.95,93.06 67.06,92.96 67.06,92.75 66.95,92.65 66.62,92.65 66.4,92.43 66.4,92.06 66.62,91.84 66.95,91.84 67.06,91.74 67.06,90.84 59.58,83.36 58.26,83.36 58.16,83.46 58.16,83.8 57.94,84.02 57.57,84.02 57.35,83.8 57.35,83.46 57.25,83.36 57.04,83.36 56.94,83.46 56.94,83.8 56.72,84.02 56.35,84.02 56.13,83.8 56.13,83.46 56.03,83.36 55.82,83.36 55.72,83.46 55.72,83.8 55.5,84.02 55.13,84.02 54.91,83.8 54.91,83.46 54.81,83.36 54.6,83.36 54.5,83.46 54.5,83.8 54.28,84.02 53.91,84.02 53.69,83.8 53.69,83.46 53.59,83.36 53.39,83.36 53.28,83.46 53.28,83.8 53.06,84.02 52.69,84.02 52.47,83.8 52.47,83.46 52.37,83.36 52.17,83.36 52.06,83.46 52.06,83.8 51.84,84.02 51.47,84.02 51.25,83.8 51.25,83.46 51.15,83.36 50.95,83.36 50.85,83.46 50.85,83.8 50.62,84.02 50.25,84.02 50.03,83.8 50.03,83.46 49.93,83.36 49.73,83.36 49.63,83.46 49.63,83.8 49.41,84.02 49.03,84.02 48.81,83.8 48.81,83.46 48.71,83.36 48.51,83.36 48.41,83.46 48.41,83.8 48.19,84.02 47.81,84.02 47.59,83.8 47.59,83.46 47.49,83.36 20.83,83.36 19.86,84.33 19.51,84.33 19.25,84.07 19.25,83.06 v3(19.68,82.63)
  BOTTOM w0.102: v3(19.68,82.63) FMC.K10
FMC_DQD+6: length 142.1
  TOP w0.102: v1(120.52,107.34) 120.52,107.04 120.85,106.72 120.85,104.62 U5.A8
  SIG3 w0.102: v3(57.07,86.44) 56.95,86.56 56.95,88.47 57.83,89.35 58.82,89.35 59.39,89.92 59.39,90.78 59.16,91 58.83,91 58.72,91.1 58.72,91.31 58.83,91.41 59.16,91.41 59.39,91.63 59.39,92 59.16,92.22 58.83,92.22 58.72,92.32 58.72,92.53 58.83,92.63 59.16,92.63 59.39,92.85 59.39,93.22 59.16,93.44 58.83,93.44 58.72,93.54 58.72,93.75 58.83,93.85 59.16,93.85 59.39,94.07 59.39,94.44 59.16,94.66 58.83,94.66 58.72,94.76 58.72,94.97 58.83,95.07 59.16,95.07 59.39,95.29 59.39,95.66 59.16,95.88 58.83,95.88 58.72,95.98 58.72,96.18 58.83,96.29 59.16,96.29 59.39,96.51 59.39,96.88 59.16,97.1 58.83,97.1 58.72,97.2 58.72,97.4 58.83,97.51 59.16,97.51 59.39,97.73 59.39,98.1 59.16,98.32 58.83,98.32 58.72,98.42 58.72,98.62 58.83,98.72 59.16,98.72 59.39,98.94 59.39,99.32 59.16,99.54 58.83,99.54 58.72,99.64 58.72,99.84 58.83,99.94 59.16,99.94 59.39,100.16 59.39,100.54 59.16,100.76 58.83,100.76 58.72,100.86 58.72,101.06 58.83,101.16 59.16,101.16 59.39,101.38 59.39,101.75 59.16,101.98 58.83,101.98 58.72,102.08 58.72,102.28 58.83,102.38 59.16,102.38 59.39,102.6 59.39,102.97 59.16,103.19 58.83,103.19 58.72,103.3 58.72,103.5 58.83,103.6 59.16,103.6 59.39,103.82 59.39,104.19 59.16,104.41 58.83,104.41 58.72,104.52 58.72,104.72 58.83,104.82 59.16,104.82 59.39,105.04 59.39,105.41 59.16,105.63 58.83,105.63 58.72,105.73 58.72,105.94 58.83,106.04 59.16,106.04 59.39,106.26 59.39,106.72 61.73,109.07 117.25,109.07 119.05,107.26 120.45,107.26 v1(120.52,107.34)
  BOTTOM w0.102: FMC.J9 18.29,81.23 51.82,81.23 57.03,86.44 v3(57.07,86.44)
FMC_DQD+7: length 142.1
  TOP w0.102: v1(119.72,98.75) U5.F7
  SIG3 w0.102: v1(119.72,98.75) 119.32,98.35 81.83,98.35 76.27,92.79 v3(76.23,92.79)
  BOTTOM w0.102: v3(76.23,92.79) 76.43,92.99 76.43,93.32 75.92,93.83 75.26,93.83 72.54,91.11 72.54,83.44 72.01,82.91 67.74,82.91 67.28,83.36 67.28,93.21 65.93,94.56 55.65,94.56 53.72,92.63 16.31,92.63 15.98,92.3 15.98,91.85 15.54,91.41 15.06,91.41 14.73,91.08 14.73,88.01 14.94,87.81 15.55,87.81 16,87.35 16,82.75 15.75,82.5 14.48,82.5 FMC.F10
FMC_DQD+8: length 142
  TOP w0.102: v1(119.71,100.75) 120.22,100.24 U5.E7
  SIG3 w0.102: v3(12.06,81.36) 12.6,81.89 46.36,81.89 46.58,82.11 46.58,82.45 46.68,82.55 46.88,82.55 46.98,82.45 46.98,82.11 47.21,81.89 47.58,81.89 47.8,82.11 47.8,82.45 47.9,82.55 48.1,82.55 48.2,82.45 48.2,82.11 48.42,81.89 48.8,81.89 49.02,82.11 49.02,82.45 49.12,82.55 49.32,82.55 49.42,82.45 49.42,82.11 49.64,81.89 50.02,81.89 50.24,82.11 50.24,82.45 50.34,82.55 50.54,82.55 50.64,82.45 50.64,82.11 50.86,81.89 51.23,81.89 51.46,82.11 51.46,82.45 51.56,82.55 51.76,82.55 51.86,82.45 51.86,82.11 52.08,81.89 52.45,81.89 52.67,82.11 52.67,82.45 52.78,82.55 52.98,82.55 53.08,82.45 53.08,82.11 53.3,81.89 53.67,81.89 53.89,82.11 53.89,82.45 54,82.55 54.2,82.55 54.3,82.45 54.3,82.11 54.52,81.89 54.89,81.89 55.11,82.11 55.11,82.45 55.21,82.55 55.42,82.55 55.52,82.45 55.52,82.11 55.74,81.89 56.11,81.89 56.33,82.11 56.33,82.45 56.43,82.55 56.64,82.55 56.74,82.45 56.74,82.11 56.96,81.89 57.33,81.89 57.55,82.11 57.55,82.45 57.65,82.55 57.86,82.55 57.96,82.45 57.96,82.11 58.18,81.89 58.55,81.89 58.77,82.11 58.77,82.45 58.87,82.55 59.08,82.55 59.18,82.45 59.18,82.11 59.4,81.89 59.77,81.89 59.99,82.11 59.99,82.47 60.09,82.58 60.29,82.58 60.4,82.47 60.4,82.11 60.62,81.89 61.24,81.89 69.8,90.45 69.8,91.82 69.58,92.04 69.24,92.04 69.14,92.14 69.14,92.35 69.24,92.45 69.58,92.45 69.8,92.67 69.8,93.04 69.58,93.26 69.24,93.26 69.14,93.36 69.14,93.56 69.24,93.67 69.58,93.67 69.8,93.89 69.8,94.26 69.58,94.48 69.24,94.48 69.14,94.58 69.14,94.78 69.24,94.89 69.58,94.89 69.8,95.11 69.8,95.48 69.58,95.7 69.24,95.7 69.14,95.8 69.14,96 69.24,96.1 69.58,96.1 69.8,96.33 69.8,96.7 69.58,96.92 69.24,96.92 69.14,97.02 69.14,97.22 69.24,97.32 69.58,97.32 69.8,97.54 69.8,97.92 69.58,98.14 69.24,98.14 69.14,98.24 69.14,98.44 69.24,98.54 69.58,98.54 69.8,98.76 69.8,99.14 69.58,99.36 69.24,99.36 69.14,99.46 69.14,99.66 69.24,99.76 69.58,99.76 69.8,99.98 69.8,101.17 69.98,101.35 112.89,101.35 113.09,101.16 119.3,101.16 v1(119.71,100.75)
  BOTTOM w0.102: FMC.E9 v3(12.06,81.36)
FMC_DQD+9: length 142.1
  TOP w0.102: U5.A6 v1(118.71,103.76)
  SIG3 w0.102: v3(63.68,91.52) 63.68,91.53 63.45,91.76 63.45,93.22 63.23,93.44 60.78,93.44 60.68,93.54 60.68,93.75 60.78,93.85 63.23,93.85 63.45,94.07 63.45,94.44 63.23,94.66 60.78,94.66 60.68,94.76 60.68,94.97 60.78,95.07 63.23,95.07 63.45,95.29 63.45,95.66 63.23,95.88 60.78,95.88 60.68,95.98 60.68,96.18 60.78,96.29 63.23,96.29 63.45,96.51 63.45,96.88 63.23,97.1 60.78,97.1 60.68,97.2 60.68,97.4 60.78,97.51 63.23,97.51 63.45,97.73 63.45,106.78 64.36,107.7 116.38,107.7 118.11,105.97 118.11,104.54 118.71,103.94 v1(118.71,103.76)
  BOTTOM w0.102: v3(63.68,91.52) 63.47,91.31 63.47,91.01 63.22,90.75 57.26,90.75 52.81,86.31 19.56,86.31 FMC.K13
FMC_DQD+10: length 142.1
  TOP w0.102: U5.A4 117.22,104.24 v1(116.71,104.76)
  SIG3 w0.102: v1(116.71,104.76) 116.66,104.71 116.66,104.37 116.76,104.27 116.93,104.27 117.11,104.44 117.11,104.92 115.6,106.43 65.13,106.43 64.72,106.02 64.72,91.06 59.36,85.7 53.3,85.7 53.08,85.92 53.08,87.35 52.98,87.45 52.78,87.45 52.67,87.35 52.67,85.92 52.45,85.7 52.08,85.7 51.86,85.92 51.86,87.35 51.76,87.45 51.56,87.45 51.46,87.35 51.46,85.92 51.23,85.7 50.86,85.7 50.64,85.92 50.64,87.35 50.54,87.45 50.34,87.45 50.24,87.35 50.24,85.92 50.02,85.7 49.64,85.7 49.42,85.92 49.42,87.35 49.32,87.45 49.12,87.45 49.02,87.35 49.02,85.92 48.8,85.7 48.42,85.7 48.2,85.92 48.2,87.35 48.1,87.45 47.9,87.45 47.8,87.35 47.8,85.92 47.58,85.7 47.21,85.7 46.98,85.92 46.98,87.35 46.88,87.45 46.68,87.45 46.58,87.35 46.58,85.92 46.36,85.7 45.99,85.7 45.77,85.92 45.77,87.35 45.66,87.45 45.46,87.45 45.36,87.35 45.36,85.92 45.14,85.7 18.44,85.7 18.41,85.67 v3(18.41,85.17)
  BOTTOM w0.102: FMC.J12 v3(18.41,85.17)
FMC_DQD+11: length 142.1
  TOP w0.102: v1(115.7,104.76) 116.22,104.24 U5.A3
  SIG3 w0.102: v3(13.34,86.44) 13.46,86.44 13.59,86.56 13.59,86.84 13.46,86.97 11.64,86.97 11.53,86.86 11.53,85.96 11.6,85.89 15.2,85.89 16.46,84.63 18.79,84.63 19.27,85.12 45.6,85.12 46.08,84.63 46.27,84.63 46.38,84.73 46.38,85.07 46.6,85.29 46.97,85.29 47.19,85.07 47.19,84.73 47.29,84.63 47.49,84.63 47.59,84.73 47.59,85.07 47.81,85.29 48.19,85.29 48.41,85.07 48.41,84.73 48.51,84.63 48.71,84.63 48.81,84.73 48.81,85.07 49.03,85.29 49.41,85.29 49.63,85.07 49.63,84.73 49.73,84.63 49.93,84.63 50.03,84.73 50.03,85.07 50.25,85.29 50.62,85.29 50.85,85.07 50.85,84.73 50.95,84.63 51.15,84.63 51.25,84.73 51.25,85.05 51.47,85.27 51.84,85.27 52.06,85.05 52.06,84.73 52.17,84.63 52.37,84.63 52.47,84.73 52.47,85.05 52.69,85.27 53.06,85.27 53.28,85.05 53.28,84.73 53.39,84.63 53.59,84.63 53.69,84.73 53.69,85.05 53.91,85.27 54.28,85.27 54.5,85.05 54.5,84.73 54.6,84.63 54.81,84.63 54.91,84.73 54.91,85.05 55.13,85.27 55.5,85.27 55.72,85.05 55.72,84.73 55.82,84.63 56.03,84.63 56.13,84.73 56.13,85.05 56.35,85.27 56.72,85.27 56.94,85.05 56.94,84.73 57.04,84.63 57.25,84.63 57.35,84.73 57.35,85.05 57.57,85.27 57.94,85.27 58.16,85.05 58.16,84.73 58.26,84.63 59.43,84.63 65.79,90.99 65.79,92.96 65.68,93.06 65.37,93.06 65.15,93.28 65.15,93.65 65.37,93.87 65.68,93.87 65.79,93.97 65.79,94.17 65.68,94.28 65.37,94.28 65.15,94.5 65.15,94.87 65.37,95.09 65.68,95.09 65.79,95.19 65.79,95.39 65.68,95.5 65.37,95.5 65.15,95.72 65.15,96.09 65.37,96.31 65.68,96.31 65.79,96.41 65.79,96.61 65.68,96.71 65.37,96.71 65.15,96.94 65.15,97.31 65.37,97.53 65.68,97.53 65.79,97.63 65.79,97.83 65.68,97.93 65.37,97.93 65.15,98.15 65.15,98.53 65.37,98.75 65.68,98.75 65.79,98.85 65.79,99.05 65.68,99.15 65.37,99.15 65.15,99.37 65.15,99.75 65.37,99.97 65.68,99.97 65.79,100.07 65.79,104.81 66.34,105.36 113.69,105.36 114.69,104.36 115.31,104.36 v1(115.7,104.76)
  BOTTOM w0.102: FMC.F13 v3(13.34,86.44)
FMC_DQD-0: length 142.1
  TOP w0.102: v1(122.7,100.75) 123.22,100.24 U5.E10
  SIG3 w0.102: v1(122.7,100.75) 122.7,100.6 122.11,100 122.11,92.57 121.89,92.35 119.46,92.35 119.1,92 119.1,91.56 118.89,91.35 76.1,91.35 61.13,76.38 55.74,76.38 55.52,76.16 55.52,75.34 55.42,75.23 55.21,75.23 55.11,75.34 55.11,76.16 54.89,76.38 54.52,76.38 54.3,76.16 54.3,75.34 54.2,75.23 53.99,75.23 53.89,75.34 53.89,76.16 53.67,76.38 53.3,76.38 53.08,76.16 53.08,75.34 52.98,75.23 52.78,75.23 52.67,75.34 52.67,76.16 52.45,76.38 52.08,76.38 51.86,76.16 51.86,75.34 51.76,75.23 51.56,75.23 51.45,75.34 51.45,76.16 51.23,76.38 50.86,76.38 50.64,76.16 50.64,75.34 50.54,75.23 50.34,75.23 50.24,75.34 50.24,76.16 50.02,76.38 49.64,76.38 49.42,76.16 49.42,75.34 49.32,75.23 49.12,75.23 49.02,75.34 49.02,76.16 48.8,76.38 48.42,76.38 48.2,76.16 48.2,75.34 48.1,75.23 47.9,75.23 47.8,75.34 47.8,76.16 47.58,76.38 46.35,76.38 43.18,73.2 12.45,73.2 12.06,73.58 v3(12.06,73.74)
  BOTTOM w0.102: FMC.E3 v3(12.06,73.74)
FMC_DQD-1: length 142.1
  TOP w0.102: v1(121.71,98.75) U5.F9
  SIG3 w0.102: v1(121.71,98.75) 121.71,99.07 121.64,99.14 72.65,99.14 72.34,98.83 72.34,97.54 72.12,97.32 71.78,97.32 71.68,97.22 71.68,97.02 71.78,96.92 72.12,96.92 72.34,96.7 72.34,96.33 72.12,96.1 71.78,96.1 71.68,96 71.68,95.8 71.78,95.7 72.12,95.7 72.34,95.48 72.34,95.11 72.12,94.89 71.78,94.89 71.68,94.78 71.68,94.58 71.78,94.48 72.12,94.48 72.34,94.26 72.34,93.89 72.12,93.67 71.78,93.67 71.68,93.56 71.68,93.36 71.78,93.26 72.12,93.26 72.34,93.04 72.34,92.67 72.12,92.45 71.78,92.45 71.68,92.35 71.68,92.14 71.78,92.04 72.12,92.04 72.34,91.82 72.34,91.45 72.12,91.23 71.78,91.23 71.68,91.13 71.68,90.92 71.78,90.82 72.12,90.82 72.34,90.6 72.34,90.14 61.54,79.35 60.62,79.35 60.4,79.57 60.4,79.91 60.29,80.01 60.09,80.01 59.99,79.91 59.99,79.27 59.77,79.04 59.4,79.04 59.18,79.27 59.18,79.91 59.08,80.01 58.87,80.01 58.77,79.91 58.77,79.27 58.55,79.04 58.18,79.04 57.96,79.27 57.96,79.91 57.86,80.01 57.65,80.01 57.55,79.91 57.55,79.27 57.33,79.04 56.96,79.04 56.74,79.27 56.74,79.91 56.64,80.01 56.43,80.01 56.33,79.91 56.33,79.27 56.11,79.04 55.74,79.04 55.52,79.27 55.52,79.91 55.42,80.01 55.21,80.01 55.11,79.91 55.11,79.27 54.89,79.04 54.52,79.04 54.3,79.27 54.3,79.91 54.2,80.01 54,80.01 53.89,79.91 53.89,79.29 53.67,79.07 53.3,79.07 53.08,79.29 53.08,79.91 52.98,80.01 52.78,80.01 52.67,79.91 52.67,79.29 52.45,79.07 52.08,79.07 51.86,79.29 51.86,79.91 51.76,80.01 51.56,80.01 51.46,79.91 51.46,79.29 51.23,79.07 50.86,79.07 50.64,79.29 50.64,79.91 50.54,80.01 50.34,80.01 50.24,79.91 50.24,79.29 50.02,79.07 49.64,79.07 49.42,79.29 49.42,79.91 49.32,80.01 49.12,80.01 49.02,79.91 49.02,79.29 48.8,79.07 48.42,79.07 48.2,79.29 48.2,79.91 48.1,80.01 47.9,80.01 47.8,79.91 47.8,79.57 47.58,79.35 46.46,79.35 45.29,80.52 19.43,80.52 19.23,80.31 19.23,79.55 19.41,79.38 19.53,79.38 19.68,79.53 v3(19.68,80.09)
  BOTTOM w0.102: FMC.K8 v3(19.68,80.09)
FMC_DQD-2: length 142.1
  TOP w0.102: v1(120.71,97.74) U5.G8
  SIG3 w0.102: v3(18.41,78.82) 18.95,78.28 45.44,78.28 45.82,78.66 46.97,78.66 47.19,78.44 47.19,77.39 47.29,77.29 47.49,77.29 47.59,77.39 47.59,78.44 47.81,78.66 48.19,78.66 48.41,78.44 48.41,77.39 48.51,77.29 48.71,77.29 48.81,77.39 48.81,78.44 49.03,78.66 49.41,78.66 49.63,78.44 49.63,77.39 49.73,77.29 49.93,77.29 50.03,77.39 50.03,78.44 50.25,78.66 50.62,78.66 50.85,78.44 50.85,77.39 50.95,77.29 51.15,77.29 51.25,77.39 51.25,78.44 51.47,78.66 51.84,78.66 52.06,78.44 52.06,77.42 52.17,77.32 52.37,77.32 52.47,77.42 52.47,78.44 52.69,78.66 53.06,78.66 53.28,78.44 53.28,77.42 53.39,77.32 53.59,77.32 53.69,77.42 53.69,78.44 53.91,78.66 54.28,78.66 54.5,78.44 54.5,77.42 54.6,77.32 54.81,77.32 54.91,77.42 54.91,78.44 55.13,78.66 55.5,78.66 55.72,78.44 55.72,77.42 55.82,77.32 56.03,77.32 56.13,77.42 56.13,78.44 56.35,78.66 56.72,78.66 56.94,78.44 56.94,77.42 57.04,77.32 57.25,77.32 57.35,77.42 57.35,78.44 57.57,78.66 57.94,78.66 58.16,78.44 58.16,77.42 58.26,77.32 58.47,77.32 58.57,77.42 58.57,78.44 58.79,78.66 59.16,78.66 59.38,78.44 59.38,77.42 59.48,77.32 59.68,77.32 59.79,77.42 59.79,78.44 60.01,78.66 61.99,78.66 75.68,92.35 117.98,92.35 118.11,92.48 118.11,93.04 118.42,93.35 120.07,93.35 121.11,94.39 121.11,98.07 120.86,98.32 120.7,98.32 120.52,98.15 120.52,97.93 v1(120.71,97.74)
  BOTTOM w0.102: FMC.J7 v3(18.41,78.82)
FMC_DQD-3: length 142.1
  TOP w0.102: v1(120.71,102.76) 121.22,102.25 U5.C8
  SIG3 w0.102: v3(14.61,78.82) 15.14,78.28 16.23,78.28 16.41,78.46 16.41,79.28 16.68,79.55 17.5,79.55 17.68,79.73 17.68,80.35 18.74,81.41 46.21,81.41 46.79,80.82 47.49,80.82 47.59,80.92 47.59,81.26 47.81,81.48 48.19,81.48 48.41,81.26 48.41,80.92 48.51,80.82 48.71,80.82 48.81,80.92 48.81,81.26 49.03,81.48 49.41,81.48 49.63,81.26 49.63,80.92 49.73,80.82 49.93,80.82 50.03,80.92 50.03,81.26 50.25,81.48 50.62,81.48 50.85,81.26 50.85,80.92 50.95,80.82 51.15,80.82 51.25,80.92 51.25,81.26 51.47,81.48 51.84,81.48 52.06,81.26 52.06,80.92 52.17,80.82 52.37,80.82 52.47,80.92 52.47,81.26 52.69,81.48 53.06,81.48 53.28,81.26 53.28,80.92 53.39,80.82 53.59,80.82 53.69,80.92 53.69,81.26 53.91,81.48 54.28,81.48 54.5,81.26 54.5,80.92 54.6,80.82 54.81,80.82 54.91,80.92 54.91,81.26 55.13,81.48 55.5,81.48 55.72,81.26 55.72,80.92 55.82,80.82 56.03,80.82 56.13,80.92 56.13,81.26 56.35,81.48 56.72,81.48 56.94,81.26 56.94,80.92 57.04,80.82 57.25,80.82 57.35,80.92 57.35,81.24 57.57,81.46 57.94,81.46 58.16,81.24 58.16,80.92 58.26,80.82 58.47,80.82 58.57,80.92 58.57,81.24 58.79,81.46 59.16,81.46 59.38,81.24 59.38,80.92 59.48,80.82 59.68,80.82 59.79,80.92 59.79,81.24 60.01,81.46 60.38,81.46 60.6,81.24 60.6,80.92 60.7,80.82 61.31,80.82 70.87,90.38 70.87,91.74 70.76,91.84 70.45,91.84 70.23,92.06 70.23,92.43 70.45,92.65 70.76,92.65 70.87,92.75 70.87,92.96 70.76,93.06 70.45,93.06 70.23,93.28 70.23,93.65 70.45,93.87 70.76,93.87 70.87,93.97 70.87,94.17 70.76,94.28 70.45,94.28 70.23,94.5 70.23,94.87 70.45,95.09 70.76,95.09 70.87,95.19 70.87,95.39 70.76,95.5 70.45,95.5 70.23,95.72 70.23,96.09 70.45,96.31 70.76,96.31 70.87,96.41 70.87,96.61 70.76,96.71 70.45,96.71 70.23,96.94 70.23,97.31 70.45,97.53 70.76,97.53 70.87,97.63 70.87,97.83 70.76,97.93 70.45,97.93 70.23,98.15 70.23,98.53 70.45,98.75 70.76,98.75 70.87,98.85 70.87,99.93 71.29,100.36 119.89,100.36 120.1,100.57 120.1,101 120.46,101.35 120.89,101.35 121.11,101.57 121.11,102.35 v1(120.71,102.76)
  BOTTOM w0.102: FMC.F8 v3(14.61,78.82)
FMC_DQD-4: length 142.1
  TOP w0.102: U5.D7 120.22,101.24 v1(119.71,101.75)
  SIG3 w0.102: v3(62.15,83.9) 62.15,84.23 68.53,90.6 68.53,91.82 68.31,92.04 68,92.04 67.89,92.14 67.89,92.35 68,92.45 68.31,92.45 68.53,92.67 68.53,93.04 68.31,93.26 68,93.26 67.89,93.36 67.89,93.56 68,93.67 68.31,93.67 68.53,93.89 68.53,94.26 68.31,94.48 68,94.48 67.89,94.58 67.89,94.78 68,94.89 68.31,94.89 68.53,95.11 68.53,95.48 68.31,95.7 68,95.7 67.89,95.8 67.89,96 68,96.1 68.31,96.1 68.53,96.33 68.53,96.7 68.31,96.92 68,96.92 67.89,97.02 67.89,97.22 68,97.32 68.31,97.32 68.53,97.54 68.53,97.92 68.31,98.14 68,98.14 67.89,98.24 67.89,98.44 68,98.54 68.31,98.54 68.53,98.76 68.53,99.14 68.31,99.36 67.97,99.36 67.87,99.46 67.87,99.66 67.97,99.76 68.31,99.76 68.53,99.98 68.53,100.35 68.31,100.58 67.97,100.58 67.87,100.68 67.87,100.88 67.97,100.98 68.31,100.98 68.53,101.2 68.53,102.26 68.89,102.62 107.22,102.62 107.69,102.15 119.59,102.15 119.71,102.03 v1(119.71,101.75)
  BOTTOM w0.102: FMC.E7 12.7,78.11 12.27,77.67 11.1,77.67 10.67,77.25 10.67,75.23 11.02,74.88 13.03,74.88 13.21,74.7 13.21,74.09 13.66,73.63 52.02,73.63 62.15,83.77 v3(62.15,83.9)
FMC_DQD-5: length 142.1
  TOP w0.102: v1(119.71,102.76) 120.22,102.25 U5.C7
  SIG3 w0.102: v1(119.71,102.76) 120.24,102.76 120.31,102.83 120.31,103.07 120.23,103.16 114.44,103.16 113.71,103.89 74.46,103.89 74.24,104.11 74.24,104.39 74.14,104.5 73.94,104.5 73.83,104.39 73.83,104.11 73.61,103.89 73.24,103.89 73.02,104.11 73.02,104.39 72.92,104.5 72.72,104.5 72.62,104.39 72.62,104.11 72.39,103.89 72.02,103.89 71.8,104.11 71.8,104.42 71.7,104.52 71.5,104.52 71.4,104.42 71.4,104.11 71.18,103.89 70.8,103.89 70.58,104.11 70.58,104.42 70.48,104.52 70.28,104.52 70.18,104.42 70.18,104.11 69.96,103.89 69.58,103.89 69.36,104.11 69.36,104.42 69.26,104.52 69.06,104.52 68.96,104.42 68.96,104.11 68.74,103.89 67.59,103.89 67.26,103.56 67.26,102.42 67.04,102.2 66.7,102.2 66.6,102.1 66.6,101.9 66.7,101.79 67.04,101.79 67.26,101.57 67.26,101.2 67.04,100.98 66.7,100.98 66.6,100.88 66.6,100.68 66.7,100.58 67.04,100.58 67.26,100.35 67.26,99.98 67.04,99.76 66.7,99.76 66.6,99.66 66.6,99.46 66.7,99.36 67.04,99.36 67.26,99.14 67.26,98.76 67.04,98.54 66.7,98.54 66.6,98.44 66.6,98.24 66.7,98.14 67.04,98.14 67.26,97.92 67.26,97.54 67.04,97.32 66.7,97.32 66.6,97.22 66.6,97.02 66.7,96.92 67.04,96.92 67.26,96.7 67.26,96.33 67.04,96.1 66.7,96.1 66.6,96 66.6,95.8 66.7,95.7 67.04,95.7 67.26,95.48 67.26,95.11 67.04,94.89 66.7,94.89 66.6,94.78 66.6,94.58 66.7,94.48 67.04,94.48 67.26,94.26 67.26,93.89 67.04,93.67 66.7,93.67 66.6,93.56 66.6,93.36 66.7,93.26 67.04,93.26 67.26,93.04 67.26,92.67 67.04,92.45 66.7,92.45 66.6,92.35 66.6,92.14 66.7,92.04 67.04,92.04 67.26,91.82 67.26,90.75 59.66,83.16 58.18,83.16 57.96,83.38 57.96,83.72 57.86,83.82 57.65,83.82 57.55,83.72 57.55,83.38 57.33,83.16 56.96,83.16 56.74,83.38 56.74,83.72 56.64,83.82 56.43,83.82 56.33,83.72 56.33,83.38 56.11,83.16 55.74,83.16 55.52,83.38 55.52,83.72 55.42,83.82 55.21,83.82 55.11,83.72 55.11,83.38 54.89,83.16 54.52,83.16 54.3,83.38 54.3,83.72 54.2,83.82 54,83.82 53.89,83.72 53.89,83.38 53.67,83.16 53.3,83.16 53.08,83.38 53.08,83.72 52.98,83.82 52.78,83.82 52.67,83.72 52.67,83.38 52.45,83.16 52.08,83.16 51.86,83.38 51.86,83.72 51.76,83.82 51.56,83.82 51.46,83.72 51.46,83.38 51.23,83.16 50.86,83.16 50.64,83.38 50.64,83.72 50.54,83.82 50.34,83.82 50.24,83.72 50.24,83.38 50.02,83.16 49.64,83.16 49.42,83.38 49.42,83.72 49.32,83.82 49.12,83.82 49.02,83.72 49.02,83.38 48.8,83.16 48.42,83.16 48.2,83.38 48.2,83.72 48.1,83.82 47.9,83.82 47.8,83.72 47.8,83.38 47.58,83.16 19.96,83.16 19.86,83.06 19.55,83.06 19.46,83.15 19.46,83.77 19.58,83.9 v3(19.68,83.9)
  BOTTOM w0.102: FMC.K11 v3(19.68,83.9)
FMC_DQD-6: length 142.1
  TOP w0.102: v1(119.53,107.67) 120.59,106.61 120.59,104.32 120.52,104.24 U5.A7
  SIG3 w0.102: v1(119.53,107.67) 119.33,107.47 119.13,107.47 117.33,109.27 61.65,109.27 59.18,106.81 59.18,106.34 59.08,106.24 58.74,106.24 58.52,106.02 58.52,105.65 58.74,105.43 59.08,105.43 59.18,105.33 59.18,105.13 59.08,105.02 58.74,105.02 58.52,104.8 58.52,104.43 58.74,104.21 59.08,104.21 59.18,104.11 59.18,103.91 59.08,103.8 58.74,103.8 58.52,103.58 58.52,103.21 58.74,102.99 59.08,102.99 59.18,102.89 59.18,102.69 59.08,102.59 58.74,102.59 58.52,102.36 58.52,101.99 58.74,101.77 59.08,101.77 59.18,101.67 59.18,101.47 59.08,101.37 58.74,101.37 58.52,101.15 58.52,100.77 58.74,100.55 59.08,100.55 59.18,100.45 59.18,100.25 59.08,100.15 58.74,100.15 58.52,99.93 58.52,99.55 58.74,99.33 59.08,99.33 59.18,99.23 59.18,99.03 59.08,98.93 58.74,98.93 58.52,98.71 58.52,98.34 58.74,98.11 59.08,98.11 59.18,98.01 59.18,97.81 59.08,97.71 58.74,97.71 58.52,97.49 58.52,97.12 58.74,96.9 59.08,96.9 59.18,96.79 59.18,96.59 59.08,96.49 58.74,96.49 58.52,96.27 58.52,95.9 58.74,95.68 59.08,95.68 59.18,95.57 59.18,95.37 59.08,95.27 58.74,95.27 58.52,95.05 58.52,94.68 58.74,94.46 59.08,94.46 59.18,94.36 59.18,94.15 59.08,94.05 58.74,94.05 58.52,93.83 58.52,93.46 58.74,93.24 59.08,93.24 59.18,93.14 59.18,92.93 59.08,92.83 58.74,92.83 58.52,92.61 58.52,92.24 58.74,92.02 59.08,92.02 59.18,91.92 59.18,91.71 59.08,91.61 58.74,91.61 58.52,91.39 58.52,91.02 58.74,90.8 59.08,90.8 59.18,90.7 59.18,90 58.73,89.55 57.74,89.55 56.74,88.55 56.74,86.77 v3(56.41,86.44)
  BOTTOM w0.102: FMC.J10 17.78,81.56 17.86,81.48 51.71,81.48 56.41,86.18 v3(56.41,86.44)
